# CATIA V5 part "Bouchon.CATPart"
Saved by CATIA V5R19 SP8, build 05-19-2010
Part number: Bouchon
Bounding box of the stored display mesh (mm): x -19 to 0, y -31.209 to 31.209, z -31.209 to 31.209
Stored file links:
  U:\Rendu_cfao_elguidj\Bouchon.CATPart
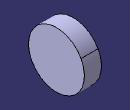
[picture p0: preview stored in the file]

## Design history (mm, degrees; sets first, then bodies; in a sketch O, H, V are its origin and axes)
Body1 (main body)
  DatumSurface1
  DatumCurve1
  Sketch1 on xy-plane, origin (0, 0, 0), H (1, 0, 0), V (0, 1, 0)
    line L1 (-19, 31.25) -> (0, 31.25)
    line L2 (0, 31.25) -> (0, 0)
    line L3 (0, 0) -> (-19, 0)
    line L4 (-19, 0) -> (-19, 31.25)
    reference intersected line E1 (-19, 32.5) -> (-19, 27) from face of DatumSurface1
    length L4 = 31.25
    horizontal: L1 H, L3 H
    vertical: L2 V, L4 V
    coincidence: L4 E1
  Shaft1: profile Sketch1, axis edge of DatumCurve1, angle 360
